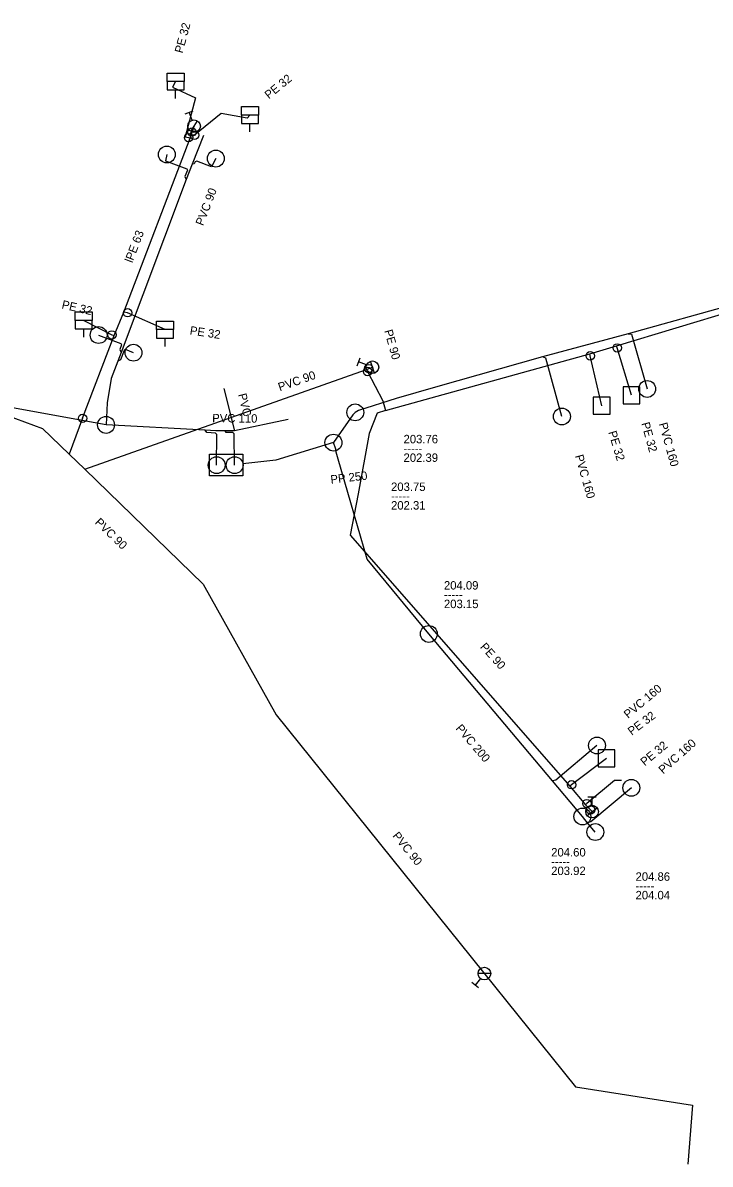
# Model space of a CAD drawing. Extents: x -686883 to -686397, y -1053920 to -1053689.
# Drawn here: x -686563.6 to -686482.1, y -1053852.9 to -1053717.7 of the extents above; entities that cross this region are included whole.
import ezdxf

# ---------------------------------------------------------------- set-up
doc = ezdxf.new("R2010")
doc.units = 0
doc.layers.add('Level 0', color=7, linetype='Continuous')

msp = doc.modelspace()

# ---------------------------------------------------------------- linework, layer by layer
at = {"layer": 'Level 0'}
for p, q in [((-686545.48, -1053724.66), (-686545.85, -1053725.31)), ((-686545.85, -1053725.31), (-686543.12, -1053726.6)), ((-686545.48, -1053726.66), (-686545.48, -1053725.66)), ((-686543.12, -1053726.6), (-686544.36, -1053731.22)), ((-686544.34, -1053728.47), (-686543.4, -1053728.13)), ((-686543.54, -1053729.24), (-686543.87, -1053728.3)), ((-686540.1, -1053728.45), (-686543.24, -1053731.02)), ((-686537.02, -1053729.02), (-686540.1, -1053728.45)), ((-686536.68, -1053728.63), (-686537.02, -1053729.02)), ((-686543.69, -1053730.58), (-686542.89, -1053729.32)), ((-686543.54, -1053730.65), (-686543.29, -1053729.95)), ((-686536.68, -1053730.63), (-686536.68, -1053729.63)), ((-686551.63, -1053751.99), (-686543.76, -1053731.38)), ((-686544.36, -1053731.22), (-686543.95, -1053731.31)), ((-686543.95, -1053731.31), (-686543.76, -1053731.38)), ((-686543.76, -1053731.38), (-686543.6, -1053730.96)), ((-686543.6, -1053730.96), (-686543.54, -1053730.65)), ((-686543.24, -1053731.02), (-686543.6, -1053730.96)), ((-686542.19, -1053731.07), (-686543.54, -1053734.46)), ((-686546.52, -1053733.31), (-686546.68, -1053734.05)), ((-686546.68, -1053734.05), (-686544.17, -1053734.99)), ((-686543.54, -1053734.46), (-686544.23, -1053736.26)), ((-686543.29, -1053734.4), (-686543.54, -1053734.46)), ((-686543.17, -1053734.19), (-686543.29, -1053734.4)), ((-686542.98, -1053734.11), (-686543.17, -1053734.19)), ((-686541.22, -1053734.77), (-686542.98, -1053734.11)), ((-686540.72, -1053733.79), (-686541.22, -1053734.77)), ((-686544.09, -1053735.18), (-686544.38, -1053735.9)), ((-686544.17, -1053734.99), (-686544.09, -1053735.18)), ((-686544.23, -1053736.26), (-686551.95, -1053756.75)), ((-686544.38, -1053735.9), (-686544.23, -1053736.26)), ((-686476.71, -1053750.33), (-686491.84, -1053754.55)), ((-686600.67, -1053751.2), (-686561.26, -1053765.76)), ((-686600.67, -1053751.2), (-686561.26, -1053765.76)), ((-686552.77, -1053754.75), (-686551.63, -1053751.99)), ((-686551.17, -1053752.06), (-686551.63, -1053751.99)), ((-686546.74, -1053754.06), (-686551.17, -1053752.06)), ((-686493.21, -1053755.99), (-686476.35, -1053750.87)), ((-686556.38, -1053752.97), (-686553.03, -1053754.69)), ((-686556.51, -1053764.57), (-686552.77, -1053754.75)), ((-686556.38, -1053754.97), (-686556.38, -1053753.97)), ((-686554.61, -1053754.7), (-686551.99, -1053755.7)), ((-686553.03, -1053754.69), (-686552.77, -1053754.75)), ((-686491.84, -1053754.55), (-686501.99, -1053757.27)), ((-686491.84, -1053754.55), (-686491.44, -1053754.59)), ((-686491.44, -1053754.59), (-686489.6, -1053761.09)), ((-686551.9, -1053755.88), (-686552.11, -1053756.41)), ((-686551.99, -1053755.7), (-686551.9, -1053755.88)), ((-686546.74, -1053756.06), (-686546.74, -1053755.06)), ((-686496.4, -1053756.93), (-686493.21, -1053755.99)), ((-686493.14, -1053756.23), (-686493.21, -1053755.99)), ((-686551.95, -1053756.75), (-686552.35, -1053757.79)), ((-686552.11, -1053756.41), (-686551.95, -1053756.75)), ((-686551.59, -1053756.52), (-686552.02, -1053757.64)), ((-686551.41, -1053756.43), (-686551.59, -1053756.52)), ((-686550.48, -1053756.79), (-686551.41, -1053756.43)), ((-686523.96, -1053758.36), (-686523.61, -1053757.42)), ((-686520.61, -1053763.63), (-686496.4, -1053756.93)), ((-686501.99, -1053757.27), (-686514.68, -1053760.88)), ((-686501.6, -1053757.45), (-686501.99, -1053757.27)), ((-686499.7, -1053764.36), (-686501.6, -1053757.45)), ((-686496.34, -1053757.17), (-686496.4, -1053756.93)), ((-686494.98, -1053763.07), (-686496.34, -1053757.17)), ((-686491.45, -1053761.84), (-686493.14, -1053756.23)), ((-686556.25, -1053770.61), (-686522.86, -1053758.78)), ((-686552.35, -1053757.79), (-686553.12, -1053759.84)), ((-686552.02, -1053757.64), (-686552.35, -1053757.79)), ((-686522.85, -1053758.24), (-686523.79, -1053757.89)), ((-686522.86, -1053758.78), (-686522.6, -1053758.68)), ((-686522.86, -1053758.78), (-686522.73, -1053759.02)), ((-686522.6, -1053758.68), (-686522.15, -1053758.51)), ((-686521.93, -1053759.22), (-686522.37, -1053757.79)), ((-686553.12, -1053759.84), (-686553.61, -1053762.75)), ((-686522.73, -1053759.02), (-686520.93, -1053762.49)), ((-686539.75, -1053761.04), (-686538.51, -1053766.06)), ((-686514.68, -1053760.88), (-686519.35, -1053762.22)), ((-686490.45, -1053760.84), (-686492.45, -1053760.84)), ((-686492.45, -1053760.84), (-686492.45, -1053762.84)), ((-686490.45, -1053762.84), (-686490.45, -1053760.84)), ((-686553.61, -1053762.75), (-686553.73, -1053765.35)), ((-686519.35, -1053762.22), (-686523.79, -1053763.63)), ((-686520.93, -1053762.49), (-686520.61, -1053763.63)), ((-686493.98, -1053762.07), (-686495.98, -1053762.07)), ((-686495.98, -1053762.07), (-686495.98, -1053764.07)), ((-686493.98, -1053764.07), (-686493.98, -1053762.07)), ((-686492.45, -1053762.84), (-686490.45, -1053762.84)), ((-686553.73, -1053765.35), (-686565.24, -1053763.24)), ((-686524.48, -1053764.17), (-686526.78, -1053767.45)), ((-686524.19, -1053763.86), (-686524.48, -1053764.17)), ((-686523.79, -1053763.63), (-686524.19, -1053763.86)), ((-686521.59, -1053763.94), (-686522.56, -1053766.38)), ((-686520.61, -1053763.63), (-686521.59, -1053763.94)), ((-686495.98, -1053764.07), (-686493.98, -1053764.07)), ((-686556.51, -1053764.57), (-686558.12, -1053768.8)), ((-686542, -1053765.97), (-686553.73, -1053765.35)), ((-686532.16, -1053764.72), (-686538.51, -1053766.06)), ((-686561.26, -1053765.76), (-686558.12, -1053768.8)), ((-686561.26, -1053765.76), (-686558.12, -1053768.8)), ((-686540.7, -1053766.04), (-686542, -1053765.97)), ((-686541.8, -1053766.25), (-686542, -1053765.97)), ((-686540.76, -1053766.32), (-686541.8, -1053766.25)), ((-686540.58, -1053766.48), (-686540.76, -1053766.32)), ((-686539.61, -1053766.05), (-686540.7, -1053766.04)), ((-686540.62, -1053770.12), (-686540.58, -1053766.48)), ((-686538.51, -1053766.06), (-686539.61, -1053766.05)), ((-686539.49, -1053766.24), (-686539.61, -1053766.05)), ((-686538.69, -1053766.26), (-686539.49, -1053766.24)), ((-686538.53, -1053766.39), (-686538.69, -1053766.26)), ((-686538.49, -1053770.12), (-686538.53, -1053766.39)), ((-686522.56, -1053766.38), (-686523.84, -1053773.51)), ((-686526.78, -1053767.45), (-686533.62, -1053769.54)), ((-686526.48, -1053768.22), (-686526.78, -1053767.45)), ((-686526.46, -1053768.59), (-686526.48, -1053768.22)), ((-686558.12, -1053768.8), (-686556.25, -1053770.61)), ((-686541.48, -1053768.83), (-686537.52, -1053768.83)), ((-686541.48, -1053771.39), (-686541.48, -1053768.83)), ((-686537.52, -1053768.83), (-686537.52, -1053771.39)), ((-686533.62, -1053769.54), (-686537.52, -1053769.98)), ((-686526.23, -1053769.42), (-686526.46, -1053768.59)), ((-686522.78, -1053781.27), (-686526.23, -1053769.42)), ((-686556.25, -1053770.61), (-686542.2, -1053784.23)), ((-686537.52, -1053771.39), (-686541.48, -1053771.39)), ((-686523.84, -1053773.51), (-686524.78, -1053778.41)), ((-686524.78, -1053778.41), (-686498.75, -1053808.14)), ((-686515.47, -1053790.12), (-686522.78, -1053781.27)), ((-686542.2, -1053784.23), (-686533.55, -1053799.71)), ((-686500.82, -1053807.53), (-686515.47, -1053790.12)), ((-686533.55, -1053799.71), (-686498.09, -1053843.78)), ((-686495.54, -1053803.34), (-686500.43, -1053807.45)), ((-686493.41, -1053803.87), (-686495.41, -1053803.87)), ((-686495.41, -1053803.87), (-686495.41, -1053805.87)), ((-686493.41, -1053805.87), (-686493.41, -1053803.87)), ((-686494.41, -1053804.87), (-686498.55, -1053807.99)), ((-686495.41, -1053805.87), (-686493.41, -1053805.87)), ((-686500.43, -1053807.45), (-686500.82, -1053807.53)), ((-686497.27, -1053811.75), (-686500.82, -1053807.53)), ((-686493.45, -1053807.5), (-686496.73, -1053810.22)), ((-686492.64, -1053807.5), (-686493.45, -1053807.5)), ((-686498.55, -1053807.99), (-686498.75, -1053808.14)), ((-686498.75, -1053808.14), (-686496.92, -1053810.38)), ((-686491.47, -1053808.36), (-686496.28, -1053812.38)), ((-686496.73, -1053810.22), (-686496.92, -1053810.38)), ((-686496.62, -1053809.42), (-686495.62, -1053809.42)), ((-686496.12, -1053810.42), (-686496.12, -1053809.42)), ((-686496.92, -1053810.38), (-686496.3, -1053810.97)), ((-686496.71, -1053811.63), (-686495.53, -1053810.71)), ((-686496.3, -1053810.97), (-686496.12, -1053811.17)), ((-686496.69, -1053812.45), (-686497.27, -1053811.75)), ((-686496.28, -1053812.38), (-686496.69, -1053812.45)), ((-686495.74, -1053813.59), (-686496.69, -1053812.45)), ((-686508.13, -1053830.37), (-686509.63, -1053830.35)), ((-686509.59, -1053832.04), (-686510.37, -1053831.41)), ((-686509.35, -1053830.94), (-686509.98, -1053831.72)), ((-686498.09, -1053843.78), (-686484.21, -1053845.94)), ((-686484.21, -1053845.94), (-686484.77, -1053852.95))]:
    msp.add_line(p, q, dxfattribs=at)
for points in [[(-686546.48, -1053724.66), (-686546.48, -1053723.66), (-686544.48, -1053723.66), (-686544.48, -1053724.66)], [(-686537.68, -1053728.63), (-686537.68, -1053727.63), (-686535.68, -1053727.63), (-686535.68, -1053728.63)], [(-686557.38, -1053752.97), (-686557.38, -1053751.97), (-686555.38, -1053751.97), (-686555.38, -1053752.97)], [(-686547.74, -1053754.06), (-686547.74, -1053753.06), (-686545.74, -1053753.06), (-686545.74, -1053754.06)]]:
    msp.add_lwpolyline(points, dxfattribs=at)
for points in [[(-686546.48, -1053725.66), (-686544.48, -1053725.66), (-686544.48, -1053724.66), (-686546.48, -1053724.66)], [(-686537.68, -1053729.63), (-686535.68, -1053729.63), (-686535.68, -1053728.63), (-686537.68, -1053728.63)], [(-686557.38, -1053753.97), (-686555.38, -1053753.97), (-686555.38, -1053752.97), (-686557.38, -1053752.97)], [(-686547.74, -1053755.06), (-686545.74, -1053755.06), (-686545.74, -1053754.06), (-686547.74, -1053754.06)]]:
    msp.add_lwpolyline(points, close=True, dxfattribs=at)
for centre, radius in [((-686543.29, -1053729.95), 0.75), ((-686543.54, -1053730.65), 0.5), ((-686543.95, -1053731.31), 0.5), ((-686543.24, -1053731.02), 0.5), ((-686546.52, -1053733.31), 1), ((-686540.72, -1053733.79), 1), ((-686551.17, -1053752.06), 0.5), ((-686554.61, -1053754.7), 1), ((-686553.03, -1053754.69), 0.5), ((-686550.48, -1053756.79), 1), ((-686493.14, -1053756.23), 0.5), ((-686496.34, -1053757.17), 0.5), ((-686522.73, -1053759.02), 0.5), ((-686522.6, -1053758.68), 0.5), ((-686522.15, -1053758.51), 0.75), ((-686489.6, -1053761.09), 1), ((-686524.19, -1053763.86), 1), ((-686556.51, -1053764.57), 0.5), ((-686499.7, -1053764.36), 1), ((-686553.73, -1053765.35), 1), ((-686526.78, -1053767.45), 1), ((-686540.62, -1053770.12), 1), ((-686538.49, -1053770.12), 1), ((-686515.47, -1053790.12), 1), ((-686495.54, -1053803.34), 1), ((-686498.55, -1053807.99), 0.5), ((-686491.47, -1053808.36), 1), ((-686496.73, -1053810.22), 0.5), ((-686497.27, -1053811.75), 1), ((-686496.12, -1053811.17), 0.75), ((-686496.3, -1053810.97), 0.5), ((-686495.74, -1053813.59), 1), ((-686508.88, -1053830.36), 0.75)]:
    msp.add_circle(centre, radius, dxfattribs=at)

# ---------------------------------------------------------------- texts
for s, rotation, p in [('PE 32', 74.976, (-686544.66, -1053721.37)), ('PE 32', 39.299, (-686534.43, -1053726.79)), ('PVC 90', 68.962, (-686542.23, -1053741.82)), ('lPE 63', 69.1, (-686550.62, -1053746.21)), ('PE 32', 347.005, (-686559.05, -1053751.53)), ('PE 32', 351.347, (-686543.85, -1053754.62)), ('PE 90', 285.68, (-686520.77, -1053754.2)), ('PVC 90', 19.509, (-686533.13, -1053761.38)), ('PVC ', 283.875, (-686538.09, -1053761.74)), ('PVC 110', 359.474, (-686541.15, -1053765.04)), ('PE 32', 285.422, (-686490.3, -1053765.17)), ('PVC 160', 285.646, (-686488.21, -1053765.22)), ('PE 32', 286.945, (-686494.22, -1053766.22)), ('PVC 160', 286.007, (-686498.16, -1053769.02)), ('PP 250', 6.437, (-686527.07, -1053772.32)), ('PVC 90', 315.934, (-686555.13, -1053776.99)), ('PE 90', 311.987, (-686509.46, -1053791.71)), ('PVC 160', 40.073, (-686491.85, -1053800.2)), ('PE 32', 36.87, (-686491.42, -1053802.19)), ('PVC 200', 310.47, (-686512.35, -1053801.35)), ('PE 32', 39.668, (-686489.88, -1053805.82)), ('PVC 160', 41.714, (-686487.7, -1053806.77)), ('PVC 90', 308.821, (-686519.84, -1053814.07))]:
    msp.add_text(s, height=1, rotation=rotation, dxfattribs=at).set_placement(p)
for s, p in [('203.76', (-686518.47, -1053767.53)), ('-----', (-686518.47, -1053768.63)), ('202.39', (-686518.47, -1053769.73)), ('203.75', (-686519.95, -1053773.18)), ('-----', (-686519.95, -1053774.28)), ('202.31', (-686519.95, -1053775.38)), ('204.09', (-686513.68, -1053784.86)), ('-----', (-686513.68, -1053785.96)), ('203.15', (-686513.68, -1053787.06)), ('204.60', (-686500.97, -1053816.49)), ('-----', (-686500.97, -1053817.59)), ('203.92', (-686500.97, -1053818.69)), ('204.86', (-686490.97, -1053819.37)), ('-----', (-686490.97, -1053820.47)), ('204.04', (-686490.97, -1053821.57))]:
    msp.add_text(s, height=1, dxfattribs=at).set_placement(p)

doc.saveas('drawing.dxf')
